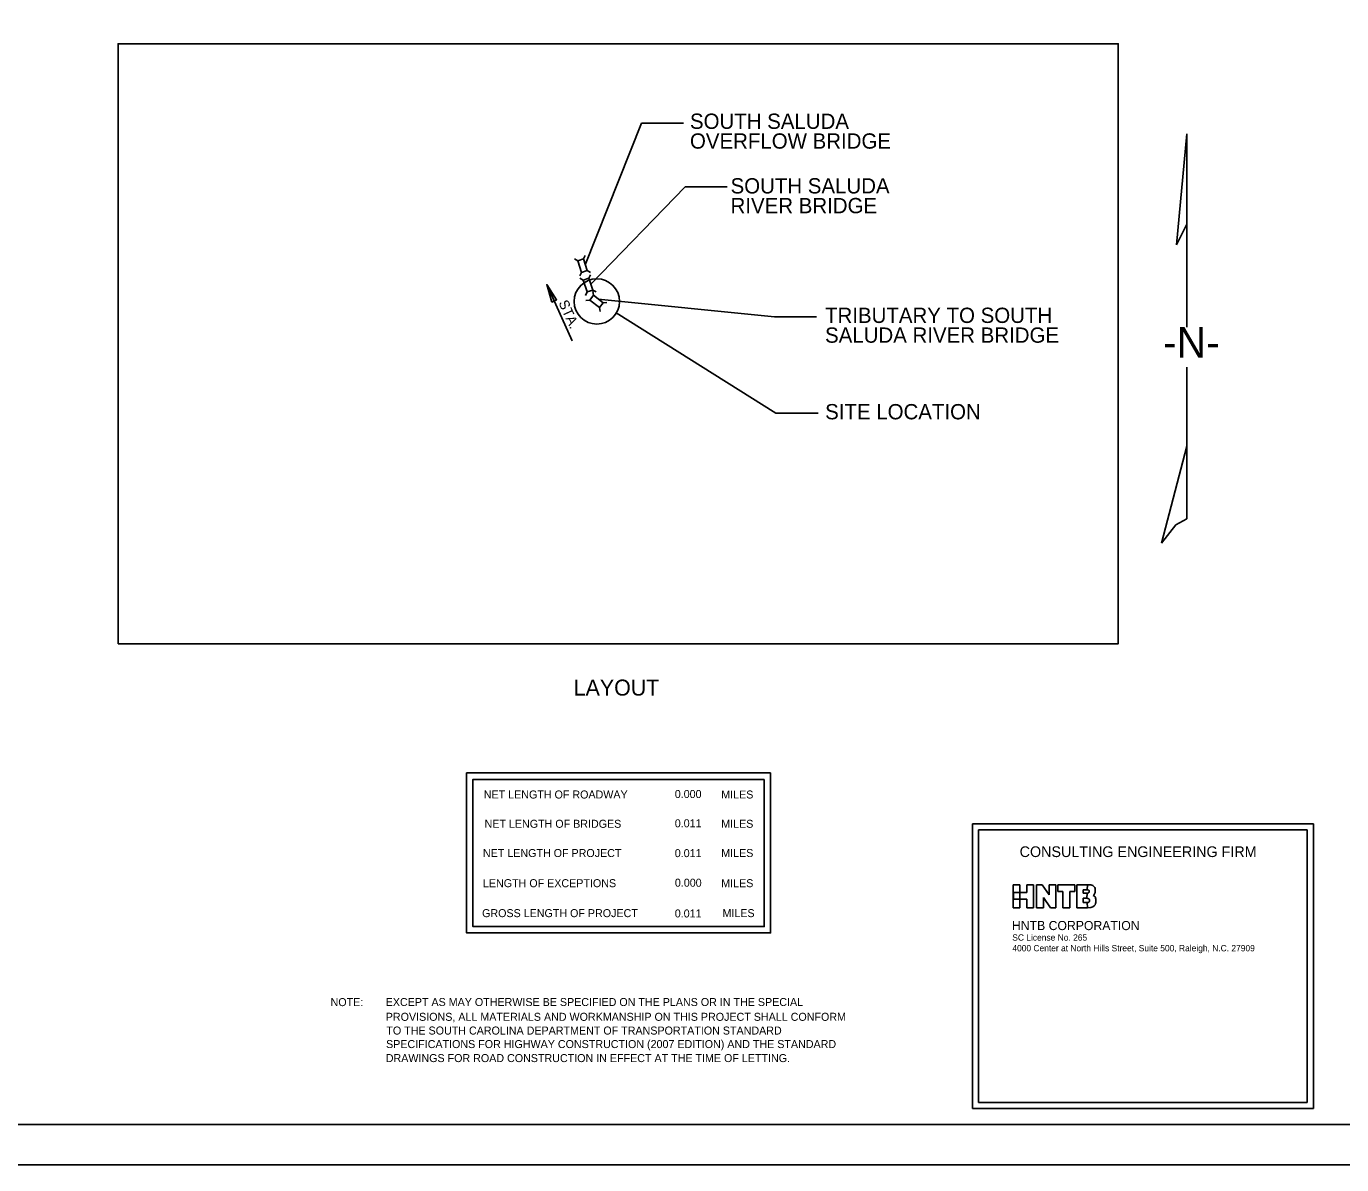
# Model space of a CAD drawing. Extents: x 0 to 4.15, y -2.5 to 1.79.
# Drawn here: x 0.946 to 2.315, y -2.5 to -1.314 of the extents above; entities that cross this region are included whole.
import ezdxf

# ---------------------------------------------------------------- set-up
doc = ezdxf.new("R2010")
doc.units = 0
for name, color, linetype in [('BR_AUTO DIMENSION', 7, 'Continuous'), ('BR_BORDER LINES', 7, 'Continuous'), ('BR_DETAILS', 7, 'Continuous'), ('BR_TEXT', 7, 'Continuous'), ('NoPlot', 7, 'Continuous'), ('V7_23', 7, 'Continuous')]:
    doc.layers.add(name, color=color, linetype=linetype)

msp = doc.modelspace()

# ---------------------------------------------------------------- linework, layer by layer
at = {"layer": 'BR_AUTO DIMENSION'}
for p, q in [((1.5277, -1.5625), (1.5862, -1.4148)), ((1.63, -1.4148), (1.5862, -1.4148)), ((2.1436, -1.5418), (2.1542, -1.4259)), ((2.1542, -1.4259), (2.1542, -1.5203)), ((1.5334, -1.5827), (1.6316, -1.4814)), ((1.6754, -1.4814), (1.6316, -1.4814)), ((2.1542, -1.5203), (2.1436, -1.5418)), ((2.1542, -1.5203), (2.1542, -1.5857)), ((2.1542, -1.5857), (2.1542, -1.6274)), ((1.5412, -1.5982), (1.7248, -1.6167)), ((1.5599, -1.6127), (1.7263, -1.7171)), ((1.7685, -1.6167), (1.7248, -1.6167)), ((2.1542, -1.6691), (2.1542, -1.7516)), ((1.7701, -1.7171), (1.7263, -1.7171)), ((2.1279, -1.8526), (2.1542, -1.7516)), ((2.1542, -1.7516), (2.1542, -1.7641)), ((2.1542, -1.7641), (2.1542, -1.8273)), ((1.931, -2.1449), (2.286, -2.1449)), ((1.931, -2.4416), (1.931, -2.1449)), ((2.286, -2.1449), (2.286, -2.4416)), ((1.9373, -2.1513), (2.2796, -2.1513)), ((1.9373, -2.4352), (1.9373, -2.1513)), ((2.2796, -2.1513), (2.2796, -2.4352)), ((2.2796, -2.4352), (1.9373, -2.4352)), ((2.286, -2.4416), (1.931, -2.4416))]:
    msp.add_line(p, q, dxfattribs=at)
msp.add_lwpolyline([(2.1542, -1.8273), (2.1429, -1.8334), (2.1279, -1.8526)], dxfattribs=at)
msp.add_circle((1.5397, -1.6007), 0.0236, dxfattribs=at)
at = {"layer": 'BR_BORDER LINES'}
msp.add_line((0.1667, -2.4582), (2.9583, -2.4582), dxfattribs=at)
msp.add_lwpolyline([(1.0411, -1.9573), (2.0828, -1.9573), (2.0828, -1.3323), (1.0411, -1.3323)], close=True, dxfattribs=at)
at = {"layer": 'BR_TEXT'}
for p, q in [((1.5198, -1.5583), (1.5163, -1.5563)), ((1.5257, -1.5564), (1.5275, -1.5527)), ((1.5238, -1.5704), (1.522, -1.5741)), ((1.5296, -1.5685), (1.5332, -1.5705)), ((1.5315, -1.5766), (1.5332, -1.573)), ((1.514, -1.6417), (1.4876, -1.5832)), ((1.5256, -1.5785), (1.522, -1.5766)), ((1.5354, -1.5888), (1.539, -1.5907)), ((1.5295, -1.5907), (1.5278, -1.5944)), ((1.5323, -1.5992), (1.5283, -1.5996)), ((1.5361, -1.5943), (1.5355, -1.5903)), ((1.5462, -1.6021), (1.5503, -1.6017)), ((1.5425, -1.607), (1.5431, -1.611))]:
    msp.add_line(p, q, dxfattribs=at)
for points in [[(1.5296, -1.5685), (1.5238, -1.5704), (1.5198, -1.5583), (1.5257, -1.5564)], [(1.4927, -1.6013), (1.4876, -1.5832), (1.4978, -1.599)], [(1.5354, -1.5888), (1.5295, -1.5907), (1.5256, -1.5785), (1.5315, -1.5766)], [(1.5462, -1.6021), (1.5425, -1.607), (1.5323, -1.5992), (1.5361, -1.5943)], [(1.7207, -2.0919), (1.4041, -2.0919), (1.4041, -2.2586), (1.7207, -2.2586)], [(1.7141, -2.0986), (1.4107, -2.0986), (1.4107, -2.2519), (1.7141, -2.2519)]]:
    msp.add_lwpolyline(points, close=True, dxfattribs=at)
at = {"layer": 'NoPlot'}
msp.add_lwpolyline([(0, -0.6667), (3, -0.6667), (3, -2.5), (0, -2.5)], close=True, dxfattribs=at)
at = {"layer": 'V7_23'}
for p, q in [((1.9733, -2.2323), (1.9733, -2.2083)), ((1.9733, -2.2083), (1.9804, -2.2083)), ((1.9804, -2.2164), (1.9736, -2.2164)), ((1.9736, -2.2164), (1.9736, -2.2235)), ((1.9804, -2.2083), (1.9804, -2.2164)), ((1.9804, -2.2235), (1.9804, -2.2164)), ((1.9804, -2.2164), (1.9875, -2.2164)), ((1.9875, -2.2164), (1.9875, -2.2083)), ((1.9875, -2.2083), (1.9946, -2.2083)), ((1.9946, -2.2083), (1.9946, -2.2323)), ((2.0037, -2.2083), (1.9978, -2.2083)), ((1.9978, -2.2083), (1.9978, -2.2323)), ((2.0108, -2.2188), (2.0037, -2.2083)), ((2.0178, -2.2083), (2.0108, -2.2083)), ((2.0108, -2.2083), (2.0108, -2.2188)), ((2.0178, -2.2323), (2.0178, -2.2083)), ((2.0198, -2.2083), (2.0198, -2.2153)), ((2.0375, -2.2083), (2.0198, -2.2083)), ((2.0198, -2.2153), (2.0251, -2.2153)), ((2.0251, -2.2153), (2.0251, -2.2323)), ((2.0322, -2.2323), (2.0322, -2.2153)), ((2.0322, -2.2153), (2.0375, -2.2153)), ((2.0375, -2.2153), (2.0375, -2.2083)), ((2.0507, -2.2083), (2.0396, -2.2083)), ((2.0396, -2.2083), (2.0396, -2.2323)), ((2.0461, -2.2172), (2.0461, -2.2137)), ((2.0461, -2.2137), (2.0503, -2.2137)), ((2.0505, -2.2172), (2.0461, -2.2172)), ((2.0502, -2.2225), (2.0505, -2.2172)), ((2.0505, -2.2172), (2.0502, -2.2225)), ((2.0503, -2.2137), (2.0507, -2.2083)), ((2.0507, -2.2083), (2.0503, -2.2137)), ((1.9804, -2.2323), (1.9733, -2.2323)), ((1.9736, -2.2235), (1.9804, -2.2235)), ((1.9875, -2.2235), (1.9804, -2.2235)), ((1.9804, -2.2235), (1.9804, -2.2323)), ((1.9875, -2.2323), (1.9875, -2.2235)), ((1.9946, -2.2323), (1.9875, -2.2323)), ((1.9978, -2.2323), (2.0048, -2.2323)), ((2.0048, -2.2323), (2.0048, -2.2215)), ((2.0048, -2.2215), (2.0121, -2.2323)), ((2.0121, -2.2323), (2.0178, -2.2323)), ((2.0251, -2.2323), (2.0322, -2.2323)), ((2.0396, -2.2323), (2.0506, -2.2323)), ((2.0461, -2.227), (2.0461, -2.2225)), ((2.0461, -2.2225), (2.0502, -2.2225)), ((2.0503, -2.227), (2.0461, -2.227)), ((2.0506, -2.2323), (2.0503, -2.227)), ((2.0503, -2.227), (2.0506, -2.2323))]:
    msp.add_line(p, q, dxfattribs=at)
for points in [[(2.0503, -2.2137), (2.0522, -2.2137), (2.0524, -2.2149), (2.0524, -2.2155), (2.0524, -2.2161), (2.052, -2.2172), (2.0505, -2.2172)], [(2.0568, -2.2194), (2.0582, -2.2182), (2.0588, -2.2165), (2.0588, -2.2153), (2.0588, -2.211), (2.0557, -2.2083), (2.0507, -2.2083), (2.0507, -2.2083), (2.0507, -2.2083), (2.0506, -2.2083)], [(2.0506, -2.2323), (2.0561, -2.2323), (2.0595, -2.2292), (2.0595, -2.2242), (2.0595, -2.2223), (2.0585, -2.2205), (2.0568, -2.2194)], [(2.0502, -2.2225), (2.0524, -2.2225), (2.0528, -2.2237), (2.0528, -2.2247), (2.0528, -2.2261), (2.0519, -2.227), (2.0503, -2.227)]]:
    msp.add_open_spline(points, degree=3, dxfattribs=at)

# ---------------------------------------------------------------- texts
at = {"layer": 'BR_AUTO DIMENSION'}
msp.add_text('-N-', height=0.03184, rotation=360, dxfattribs=at).set_placement((2.1294, -1.6591))
at = {"layer": 'BR_DETAILS'}
for s, height, p in [('LAYOUT', 0.01667, (1.5156, -2.0113)), ('NOTE:', 0.00833, (1.2624, -2.3348)), ('EXCEPT AS MAY OTHERWISE BE SPECIFIED ON THE PLANS OR IN THE SPECIAL ', 0.008334, (1.3198, -2.3347)), ('PROVISIONS, ALL MATERIALS AND WORKMANSHIP ON THIS PROJECT SHALL CONFORM ', 0.008334, (1.3199, -2.3501)), ('TO THE SOUTH CAROLINA DEPARTMENT OF TRANSPORTATION STANDARD ', 0.008334, (1.3205, -2.3644)), ('SPECIFICATIONS FOR HIGHWAY CONSTRUCTION (2007 EDITION) AND THE STANDARD', 0.008334, (1.3202, -2.3785)), ('DRAWINGS FOR ROAD CONSTRUCTION IN EFFECT AT THE TIME OF LETTING.', 0.008334, (1.3199, -2.3931))]:
    msp.add_text(s, height=height, dxfattribs=at).set_placement(p)
at = {"layer": 'BR_TEXT'}
for s, height, rotation, p in [('SOUTH SALUDA ', 0.015922, 360, (1.6367, -1.4209)), ('OVERFLOW BRIDGE', 0.015922, 360, (1.6367, -1.4415)), ('SOUTH SALUDA ', 0.015922, 360, (1.679, -1.4882)), ('RIVER BRIDGE', 0.015922, 360, (1.679, -1.5088)), ('STA.', 0.01042, 294.3217, (1.4996, -1.602)), ('TRIBUTARY TO SOUTH ', 0.015922, 360, (1.7774, -1.6231)), ('SALUDA RIVER BRIDGE', 0.015922, 360, (1.7774, -1.6437)), ('SITE LOCATION ', 0.015922, 360, (1.7775, -1.7235)), ('CONSULTING ENGINEERING FIRM', 0.011145, 0, (1.9801, -2.1795))]:
    msp.add_text(s, height=height, rotation=rotation, dxfattribs=at).set_placement(p)
for s, height, p in [('0.000', 0.00833, (1.6209, -2.118)), ('NET LENGTH OF ROADWAY', 0.008333, (1.422, -2.1185)), ('MILES', 0.00833, (1.6693, -2.1185)), ('NET LENGTH OF BRIDGES', 0.008333, (1.4228, -2.149)), ('0.011', 0.00833, (1.6209, -2.1485)), ('MILES', 0.00833, (1.6693, -2.149)), ('NET LENGTH OF PROJECT', 0.008333, (1.4211, -2.1795)), ('0.011', 0.00833, (1.6209, -2.1796)), ('MILES', 0.00833, (1.6693, -2.1795)), ('LENGTH OF EXCEPTIONS', 0.008333, (1.4211, -2.2109)), ('0.000', 0.00833, (1.621, -2.2104)), ('MILES', 0.00833, (1.6693, -2.2109)), ('GROSS LENGTH OF PROJECT', 0.008333, (1.4202, -2.2421)), ('0.011', 0.00833, (1.6209, -2.2424)), ('MILES', 0.00833, (1.6706, -2.2421)), ('HNTB CORPORATION', 0.009516, (1.9721, -2.2556)), ('SC License No. 265', 0.006558, (1.9724, -2.2666)), ('4000 Center at North Hills Street, Suite 500, Raleigh, N.C. 27909', 0.006558, (1.9725, -2.2777))]:
    msp.add_text(s, height=height, dxfattribs=at).set_placement(p)

doc.saveas('drawing.dxf')
